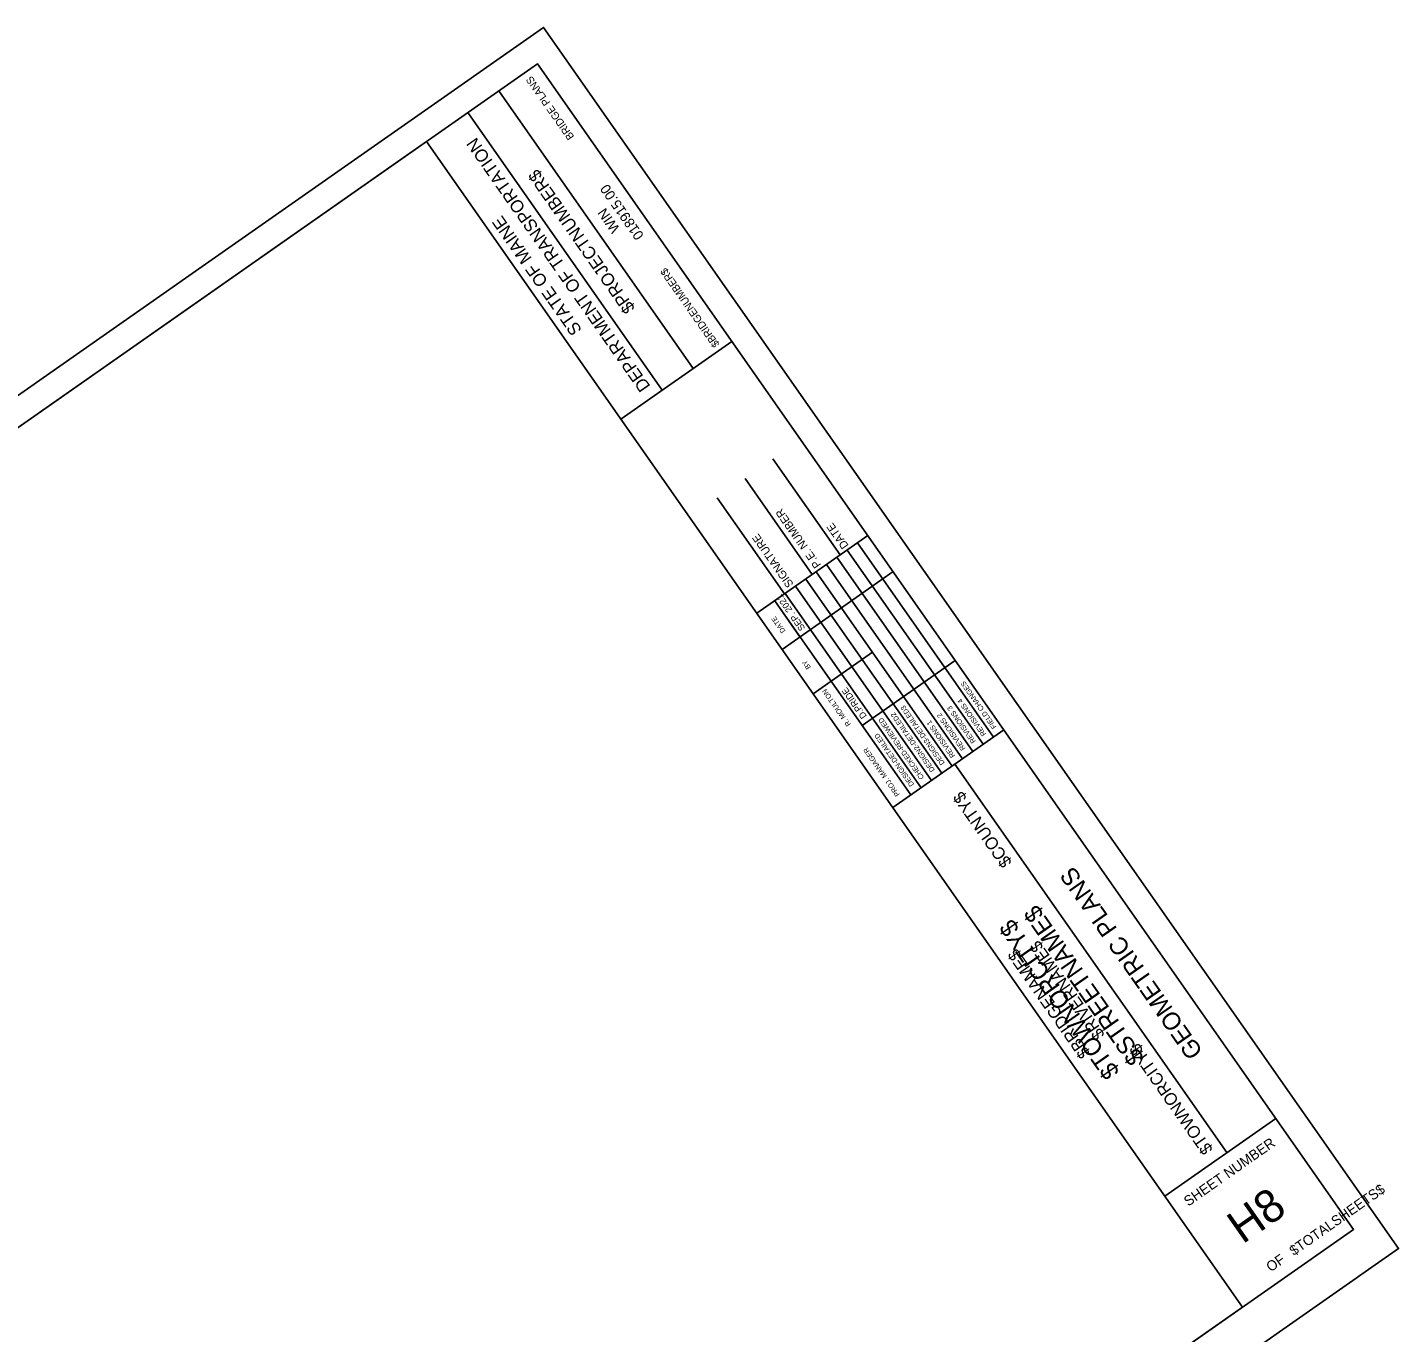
# Model space of a CAD drawing. Extents: x 1746268 to 1747280, y 464071 to 465009.
# Drawn here: x 1746774 to 1747280, y 464528 to 465009 of the extents above; entities that cross this region are included whole.
import ezdxf

# ---------------------------------------------------------------- set-up
doc = ezdxf.new("R2010")
doc.units = 0
for name, color, linetype in [('ANNOTATION', 7, 'Continuous'), ('CLIPS', 7, 'Continuous'), ('DIMENSIONS', 7, 'Continuous'), ('HIGHWAY_TITLE', 7, 'Continuous'), ('PLOT BOUNDARY', 7, 'Continuous')]:
    doc.layers.add(name, color=color, linetype=linetype)

msp = doc.modelspace()

# ---------------------------------------------------------------- linework, layer by layer
at = {"layer": 'CLIPS'}
msp.add_lwpolyline([(1746306.69, 464536.88), (1746921.05, 464967.06), (1747222.18, 464537), (1746607.82, 464106.82)], close=True, dxfattribs=at)
at = {"layer": 'DIMENSIONS'}
for p, q in [((1747019.48, 464883.36), (1746947.78, 464985.76)), ((1747008.03, 464875.35), (1746936.33, 464977.74)), ((1747222.18, 464537), (1746921.05, 464967.06)), ((1746992.77, 464864.64), (1747033.73, 464893.32)), ((1747073.65, 464814.51), (1747048.85, 464849.93)), ((1747063.41, 464807.34), (1747038.61, 464842.76)), ((1747053.17, 464800.17), (1747028.37, 464835.59)), ((1747042.93, 464793), (1747083.89, 464821.68)), ((1747093.12, 464721.33), (1747134.08, 464750)), ((1747216.39, 464594.01), (1747116.02, 464737.36)), ((1747193.5, 464577.97), (1747234.45, 464606.65))]:
    msp.add_line(p, q, dxfattribs=at)
msp.add_lwpolyline([(1746306.69, 464536.88), (1746962.01, 464995.74), (1747263.14, 464565.68), (1746607.82, 464106.82)], close=True, dxfattribs=at)
for points in [[(1747130.26, 464747.35), (1747080.08, 464819.01)], [(1747122.62, 464742), (1747072.44, 464813.67)], [(1747126.44, 464744.68), (1747076.26, 464816.34)], [(1747052.25, 464779.69), (1747093.21, 464808.37)], [(1747114.99, 464736.66), (1747064.81, 464808.32)], [(1747118.81, 464739.33), (1747068.63, 464811)], [(1747057.18, 464802.98), (1747107.36, 464731.32)], [(1747111.18, 464733.99), (1747061, 464805.65)], [(1747058.87, 464784.32), (1747049.55, 464797.63)], [(1747103.54, 464728.64), (1747053.36, 464800.31)], [(1747099.73, 464725.97), (1747051.57, 464794.74)], [(1747070.34, 464767.94), (1747085.6, 464778.63)], [(1747081.81, 464751.56), (1747116.15, 464775.6)], [(1747063.72, 464763.31), (1747070.34, 464767.94)]]:
    msp.add_lwpolyline(points, dxfattribs=at)
at = {"layer": 'PLOT BOUNDARY'}
msp.add_lwpolyline([(1746583.44, 464071.08), (1747279.72, 464558.62), (1746964.26, 465009.16), (1746267.98, 464521.62)], close=True, dxfattribs=at)

# ---------------------------------------------------------------- texts
at = {"layer": 'ANNOTATION'}
for s, height, p in [('BRIDGE PLANS', 2.795, (1746975.7, 464968.85)), ('$BRIDGENUMBER$', 2.795, (1747029.31, 464892.28)), ('$COUNTY$', 4.536, (1747137.27, 464701.16)), ('$RIVERNAME$', 4.5358, (1747171.55, 464637.58)), ('$BRIDGENAME$', 4.5358, (1747166.16, 464630.67)), ('$TOWNORCITY$', 4.5358, (1747211.43, 464595.25))]:
    msp.add_text(s, height=height, rotation=125, dxfattribs=at).set_placement(p)
at = {"layer": 'DIMENSIONS'}
for s, height, rotation, p in [('DEPARTMENT OF TRANSPORTATION', 4.6588, 125, (1747003.86, 464876.75)), ('$PROJECTNUMBER$', 4.6588, 125, (1746998.22, 464905.6)), ('018915.00', 3.726, 125, (1747001.45, 464932.4)), ('STATE OF MAINE', 4.6588, 125, (1746978.6, 464897.56)), ('WIN', 3.726, 125, (1746992.6, 464934.94)), ('P.E. NUMBER', 2.9528, 125, (1747066.79, 464810.88)), ('SIGNATURE', 2.953, 125, (1747056.64, 464803.77)), ('DATE', 2.953, 125, (1747076.95, 464818)), ('SEP. 2021', 2.423, 125, (1747060.92, 464787.56)), ('DATE', 1.857, 125, (1747053.62, 464786.49)), ('BY', 1.857, 125, (1747063, 464773.09)), ('FIELD CHANGES', 1.8637, 125, (1747131.46, 464751.15)), ('R. MOULTON', 1.864, 125, (1747077.72, 464752.07)), ('D.PRIDE', 2.423, 125, (1747083.64, 464755.11)), ('REVISIONS 4', 1.8637, 125, (1747127.64, 464748.48)), ('DESIGN2-DETAILED2', 1.8637, 125, (1747108.72, 464735.23)), ('DESIGN3-DETAILED3', 1.8637, 125, (1747112.38, 464737.79)), ('REVISIONS 2', 1.8637, 125, (1747120.01, 464743.14)), ('REVISIONS 3', 1.8637, 125, (1747123.83, 464745.81)), ('CHECKED-REVIEWED', 1.8637, 125, (1747104.75, 464732.45)), ('REVISIONS 1', 1.8637, 125, (1747116.2, 464740.46)), ('DESIGN-DETAILED', 1.8637, 125, (1747101.08, 464729.88)), ('PROJ. MANAGER', 1.8637, 125, (1747095.83, 464726.21)), ('GEOMETRIC PLANS', 6.5214, 125, (1747207.8, 464631.33)), ('SHEET NUMBER', 3.7264, 35, (1747202.14, 464574.04)), ('H8', 12.097, 35, (1747222.16, 464560.07)), ('$TOTALSHEETS$', 3.7264, 35, (1747241.09, 464555.82)), ('OF', 3.726, 35, (1747232.54, 464549.83))]:
    msp.add_text(s, height=height, rotation=rotation, dxfattribs=at).set_placement(p)
at = {"layer": 'HIGHWAY_TITLE'}
for s, p in [('$STREETNAME$', (1747186.11, 464629.13)), ('$TOWNORCITY$', (1747177.05, 464623.89))]:
    msp.add_text(s, height=6.5214, rotation=125, dxfattribs=at).set_placement(p)

doc.saveas('drawing.dxf')
